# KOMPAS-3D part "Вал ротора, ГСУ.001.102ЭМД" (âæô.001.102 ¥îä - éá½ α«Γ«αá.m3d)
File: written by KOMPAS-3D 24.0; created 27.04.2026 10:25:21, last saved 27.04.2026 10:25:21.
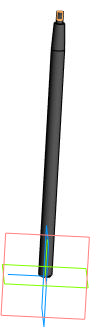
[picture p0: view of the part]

Document properties: Автор: USG_411; Полное имя файла: C:\Users\USG_411\Desktop\ГМ2704_411-15\ГСУ.001.102 ЭМД - Вал ротора.m3d

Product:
- Part/product: Вал ротора  | designation ГСУ.001.102ЭМД
    Масса: 0.060181

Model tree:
1. Эскиз:1
2. Элемент вращения:1
     Угол 1 = 360
3. Условное изображение резьбы:1  (with: Грань.Элемент вращения:1, Ребро.Элемент вращения:1)  (labels: M4; cil0_24705-2004 coarse)
     Длина резьбы = 5; Шаг резьбы = 0.7; Номинальный диаметр резьбы = 4
4. Подгонка:1  (with: Грань.Элемент вращения:1)
5. Фаска:1  (with: Ребро.Элемент вращения:1)
     Угол = 45; Длина 1 = 1; Длина 2 = 1

Referenced files in D:\КОМПАС V24\Libs\EasySteel\: Rolled metal.kle, StandartSolutions.kle, DSTVProperties.lpt
Referenced files in D:\КОМПАС V24\Templates\: Констр. чертеж А3 гориз. перв. лист.cdt
Referenced files in D:\КОМПАС V24\Libs\EasySteel\BeltEndings\: 
Referenced files in D:\КОМПАС V24\Libs\EasySteel\Punctures\: 
Referenced files in D:\КОМПАС V24\Libs\EasySteel\Insulations\: 
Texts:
  Уголок равнополочный по ГОСТ 8509-93 (Спец)
  config2DpacketName
  config2DstdSizeID
  Констр. чертеж А3 гориз. перв. лист.cdt
  Болт ГОСТ 22353-77
  Шайба ГОСТ 22355-77
  Гайка ГОСТ 22354-77
  Нормальная пружинная шайба ГОСТ 6402-70 (исп. 1)
  SeaRox SL 436
  ГСУ.001.102
  ГСУ.001.102 ЭМД
  Линейный размер с обрывом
